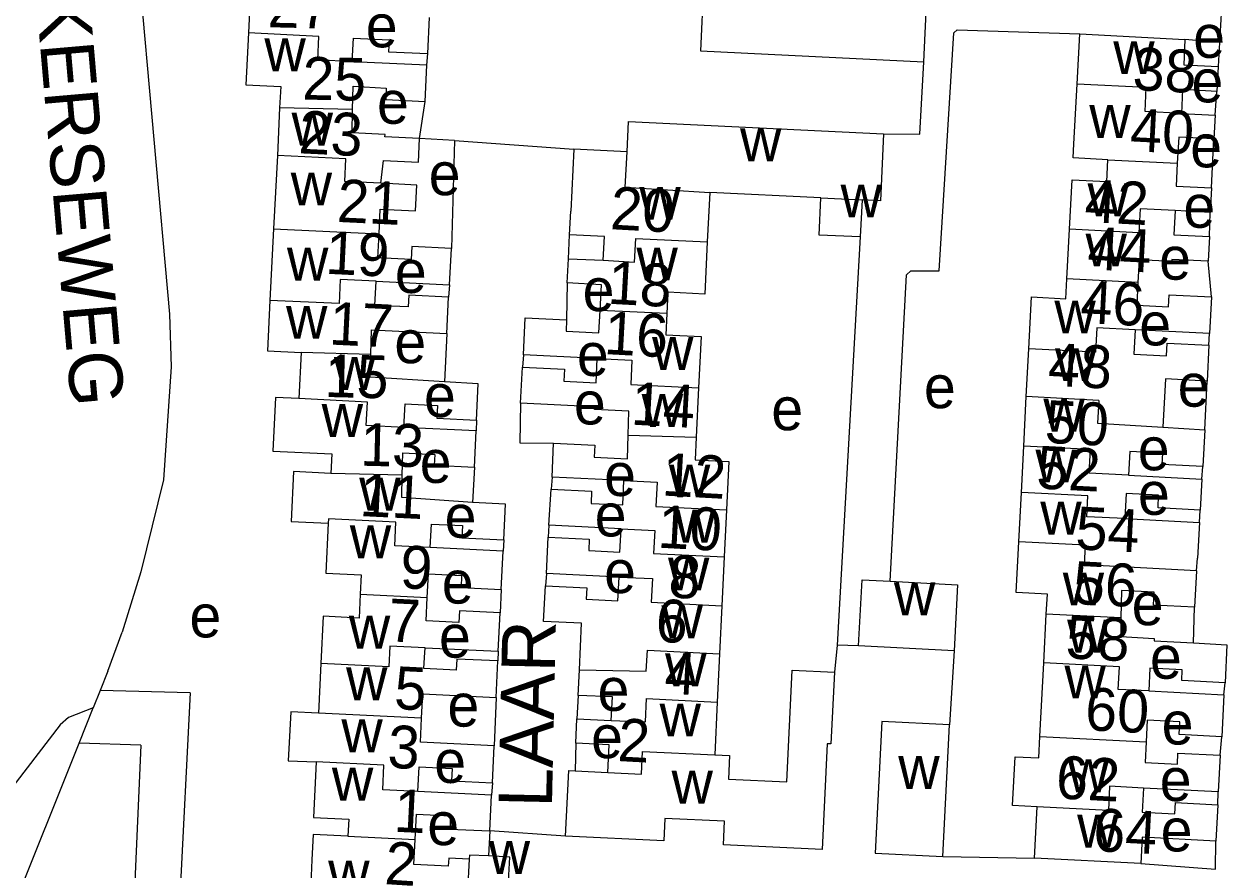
# Model space of a CAD drawing. Extents: x 163026 to 166241, y 382475 to 384501.
# Drawn here: x 164331.2 to 164443.6, y 383663 to 383742 of the extents above; entities that cross this region are included whole.
import ezdxf

# ---------------------------------------------------------------- set-up
doc = ezdxf.new("R2010")
doc.units = 0
for name, color, linetype in [('BLT_Basislijn', 7, 'Continuous'), ('BLT_Bebouwing', 7, 'Continuous'), ('BLT_Centroide', 7, 'Continuous'), ('BLT_Huisnummer', 7, 'Continuous'), ('BLT_Huisnummer_ tussenligend', 7, 'Continuous'), ('BLT_Onderverdeling_panden', 7, 'Continuous'), ('BLT_Straatnaam', 7, 'Continuous')]:
    doc.layers.add(name, color=color, linetype=linetype)

msp = doc.modelspace()

# ---------------------------------------------------------------- linework, layer by layer
at = {"layer": 'BLT_Basislijn'}
for p, q in [((164443.1, 383743.49), (164442.92, 383740.26)), ((164442.92, 383740.26), (164439.68, 383740.54)), ((164442.92, 383740.26), (164442.79, 383738)), ((164368.85, 383738.12), (164368.93, 383739.21)), ((164368.17, 383731.29), (164368.68, 383734.75)), ((164442.51, 383733.46), (164442.67, 383735.69)), ((164371.42, 383731.11), (164368.17, 383731.29)), ((164371.42, 383731.11), (164371.14, 383721.02)), ((164371.42, 383731.11), (164382.57, 383730.29)), ((164382.57, 383730.29), (164382.29, 383724.49)), ((164387.55, 383730.05), (164382.57, 383730.29)), ((164442.16, 383726.67), (164442.39, 383731.24)), ((164441.97, 383722.13), (164442.04, 383724.38)), ((164382.08, 383720.06), (164382.18, 383722.29)), ((164409.34, 383722.09), (164407.18, 383683.98)), ((164442.15, 383716.5), (164441.85, 383719.82)), ((164381.97, 383717.79), (164381.9, 383714.34)), ((164370.96, 383717.62), (164370.88, 383716.48)), ((164370.72, 383713.08), (164370.49, 383708.57)), ((164441.92, 383711.98), (164441.98, 383713.06)), ((164377.88, 383711.08), (164377.77, 383709.94)), ((164441.53, 383704.08), (164441.75, 383708.63)), ((164373.5, 383704.99), (164373.45, 383703.97)), ((164373.29, 383700.6), (164373.1, 383697.28)), ((164441.24, 383699.48), (164441.35, 383700.65)), ((164380.54, 383699.66), (164380.45, 383698.53)), ((164441.03, 383695.42), (164441.09, 383696.58)), ((164380.24, 383695.17), (164380.18, 383694.06)), ((164376.05, 383693.81), (164375.98, 383692.74)), ((164440.77, 383690.9), (164440.86, 383692.09)), ((164380.02, 383690.65), (164379.92, 383689.52)), ((164375.8, 383689.18), (164375.69, 383686.98)), ((164440.49, 383684.17), (164440.57, 383687.5)), ((164339.05, 383681.53), (164340.37, 383685.18)), ((164375.52, 383683.41), (164375.49, 383682.49)), ((164407.18, 383683.98), (164406.92, 383681.45)), ((164409.19, 383683.9), (164407.18, 383683.98)), ((164418.12, 383683.44), (164417.69, 383676.52)), ((164339.05, 383681.53), (164338.33, 383679.74)), ((164338.33, 383679.74), (164337.68, 383678.11)), ((164346.72, 383679.51), (164338.33, 383679.74)), ((164443.32, 383679.33), (164443.42, 383680.46)), ((164346.72, 383679.51), (164343.92, 383624)), ((164375.33, 383679.07), (164375.15, 383674.56)), ((164382.99, 383679.28), (164382.87, 383677.09)), ((164336.35, 383674.8), (164337.68, 383678.11)), ((164442.97, 383673.68), (164443.12, 383675.42)), ((164342.12, 383674.64), (164336.35, 383674.8)), ((164342.12, 383674.64), (164340.03, 383627.27)), ((164382.76, 383674.82), (164382.71, 383672.22)), ((164374.99, 383671.1), (164374.89, 383669.96)), ((164442.74, 383669.05), (164442.79, 383670.26)), ((164381.8, 383666.12), (164374.73, 383666.61)), ((164417.05, 383664.23), (164425.62, 383664.07))]:
    msp.add_line(p, q, dxfattribs=at)
for points in [[(164341.78, 383755.48), (164341.89, 383747.55), (164344.79, 383714.89), (164344.95, 383709.95), (164344.23, 383699.4), (164342.12, 383690.8), (164340.37, 383685.18)], [(164412.12, 383689.93), (164413.66, 383718.55), (164414.07, 383718.93), (164416.72, 383718.93), (164418.08, 383741.15), (164418.4, 383741.42), (164429.84, 383741.05)], [(164411.52, 383731.71), (164414.92, 383731.68), (164415.28, 383738.46)], [(164377.6, 383706.56), (164377.54, 383702.86), (164380.69, 383702.82)], [(164337.68, 383678.11), (164335.37, 383677.2), (164334.58, 383676.53), (164314.42, 383650.27)], [(164340.03, 383627.27), (164325.55, 383639.16), (164324.19, 383640.57), (164323.75, 383643.4), (164336.35, 383674.8)], [(164374.73, 383666.61), (164374.6, 383664.28)], [(164435.54, 383663.56), (164442.52, 383663.06), (164442.57, 383665.66)]]:
    msp.add_lwpolyline(points, dxfattribs=at)
at = {"layer": 'BLT_Bebouwing'}
for p, q in [((164352.38, 383745.55), (164352.17, 383741.15)), ((164415.28, 383738.46), (164415.58, 383744.61)), ((164368.93, 383739.21), (164369.09, 383742.59)), ((164429.6, 383736.37), (164429.84, 383741.05)), ((164429.84, 383741.05), (164439.68, 383740.54)), ((164368.68, 383734.75), (164368.85, 383738.12)), ((164442.79, 383738), (164442.67, 383735.69)), ((164355.09, 383734.15), (164354.88, 383729.71)), ((164442.51, 383733.46), (164442.39, 383731.24)), ((164387.39, 383726.75), (164387.55, 383730.05)), ((164395.28, 383726.24), (164395.05, 383721.63)), ((164405.67, 383725.74), (164395.28, 383726.24)), ((164442.16, 383726.67), (164442.04, 383724.38)), ((164409.51, 383725.55), (164409.34, 383722.09)), ((164382.18, 383722.29), (164382.29, 383724.49)), ((164428.65, 383718.17), (164428.89, 383722.82)), ((164441.97, 383722.13), (164441.85, 383719.82)), ((164370.96, 383717.62), (164371.14, 383721.02)), ((164381.97, 383717.79), (164382.08, 383720.06)), ((164382.08, 383720.06), (164385.33, 383719.91)), ((164370.72, 383713.08), (164370.88, 383716.48)), ((164442.15, 383716.5), (164441.98, 383713.06)), ((164357.09, 383711.31), (164356.88, 383706.99)), ((164424.85, 383707.18), (164425.09, 383711.65)), ((164441.92, 383711.98), (164441.75, 383708.63)), ((164377.6, 383706.56), (164377.77, 383709.94)), ((164394.24, 383708.01), (164394.02, 383703.4)), ((164424.61, 383702.56), (164424.85, 383707.18)), ((164437.6, 383704.33), (164441.53, 383704.08)), ((164373.29, 383700.6), (164373.45, 383703.97)), ((164441.53, 383704.08), (164441.35, 383700.65)), ((164380.54, 383699.66), (164380.69, 383702.82)), ((164424.39, 383698.23), (164424.61, 383702.56)), ((164441.24, 383699.48), (164441.09, 383696.58)), ((164380.24, 383695.17), (164380.45, 383698.53)), ((164424.15, 383693.63), (164424.39, 383698.23)), ((164396.85, 383696.59), (164396.63, 383692.2)), ((164441.03, 383695.42), (164440.86, 383692.09)), ((164380.02, 383690.65), (164380.18, 383694.06)), ((164375.8, 383689.18), (164375.98, 383692.74)), ((164396.63, 383692.2), (164396.41, 383687.65)), ((164440.77, 383690.9), (164440.57, 383687.5)), ((164396.41, 383687.65), (164396.2, 383683.16)), ((164375.52, 383683.41), (164375.69, 383686.98)), ((164426.49, 383682.31), (164426.72, 383686.87)), ((164396.2, 383683.16), (164395.98, 383678.65)), ((164418.12, 383683.44), (164409.19, 383683.9)), ((164358.95, 383682.24), (164358.73, 383677.62)), ((164375.33, 383679.07), (164375.49, 383682.49)), ((164382.99, 383679.28), (164383.11, 383681.65)), ((164443.32, 383679.33), (164443.12, 383675.42)), ((164382.76, 383674.82), (164382.87, 383677.09)), ((164417.05, 383664.23), (164417.69, 383676.52)), ((164374.99, 383671.1), (164375.15, 383674.56)), ((164442.97, 383673.68), (164442.79, 383670.26)), ((164382.71, 383672.22), (164385.76, 383672.07)), ((164374.73, 383666.61), (164374.89, 383669.96)), ((164425.62, 383664.07), (164425.87, 383668.88)), ((164442.74, 383669.05), (164442.57, 383665.66)), ((164435.54, 383663.56), (164425.62, 383664.07))]:
    msp.add_line(p, q, dxfattribs=at)
for points in [[(164394.7, 383745.62), (164394.41, 383739.47), (164415.28, 383738.46)], [(164352.17, 383741.15), (164351.93, 383736.3), (164355.19, 383736.14), (164355.09, 383734.15)], [(164361.87, 383738.46), (164361.98, 383740.66), (164365.32, 383740.5), (164365.26, 383739.38), (164368.93, 383739.21)], [(164439.68, 383740.54), (164439.56, 383738.17), (164442.79, 383738)], [(164368.85, 383738.12), (164361.87, 383738.46)], [(164361.91, 383733.99), (164361.96, 383736.16), (164365.06, 383736), (164365.01, 383734.93), (164368.68, 383734.75)], [(164432.48, 383729.3), (164429.24, 383729.47), (164429.31, 383730.78), (164429.6, 383736.37)], [(164442.67, 383735.69), (164439.46, 383735.86), (164439.35, 383733.62)], [(164368.17, 383731.29), (164364.93, 383731.45), (164364.94, 383731.67), (164361.86, 383731.82), (164361.91, 383733.99)], [(164439.35, 383733.62), (164442.51, 383733.46)], [(164387.55, 383730.05), (164387.68, 383732.86), (164411.52, 383731.71)], [(164364.55, 383727.1), (164364.8, 383729.22), (164368.06, 383729.06), (164368.17, 383731.29)], [(164411.52, 383731.71), (164411.22, 383725.47), (164409.51, 383725.55)], [(164442.39, 383731.24), (164439.09, 383731.41), (164438.96, 383728.97)], [(164354.88, 383729.71), (164354.53, 383722.86)], [(164428.89, 383722.82), (164429.13, 383727.44), (164432.38, 383727.27), (164432.48, 383729.3)], [(164438.96, 383728.97), (164438.85, 383726.84), (164442.16, 383726.67)], [(164364.38, 383722.38), (164364.49, 383724.7), (164367.8, 383724.54), (164367.92, 383726.94), (164364.55, 383727.1)], [(164409.34, 383722.09), (164405.5, 383722.27), (164405.67, 383725.74)], [(164438.77, 383724.55), (164438.65, 383722.3), (164441.97, 383722.13)], [(164442.04, 383724.38), (164438.77, 383724.55)], [(164354.53, 383722.86), (164354.19, 383716.17)], [(164371.14, 383721.02), (164367.43, 383721.2), (164367.37, 383719.98), (164364.27, 383720.13), (164364.38, 383722.38)], [(164385.33, 383719.91), (164385.44, 383722.13), (164382.18, 383722.29)], [(164395.05, 383721.63), (164394.82, 383716.76), (164391.37, 383716.93), (164391.28, 383714.93)], [(164441.85, 383719.82), (164438.46, 383719.99), (164438.45, 383719.79), (164435.4, 383719.95), (164435.29, 383717.83)], [(164370.88, 383716.48), (164367.15, 383716.66), (164367.1, 383715.55), (164363.99, 383715.7), (164364.1, 383717.95)], [(164364.1, 383717.95), (164370.96, 383717.62)], [(164385.03, 383715.23), (164385.15, 383717.63), (164381.97, 383717.79)], [(164425.09, 383711.65), (164425.34, 383716.49), (164428.55, 383716.32), (164428.65, 383718.17)], [(164435.29, 383717.83), (164435.18, 383715.71), (164438.15, 383715.56), (164438.21, 383716.7), (164442.15, 383716.5)], [(164354.19, 383716.17), (164353.96, 383711.46), (164357.09, 383711.31)], [(164377.88, 383711.08), (164378.04, 383714.53), (164381.9, 383714.34)], [(164381.9, 383714.34), (164381.85, 383713.3), (164384.93, 383713.15), (164385.03, 383715.23)], [(164391.28, 383714.93), (164391.18, 383712.94), (164394.48, 383712.78), (164394.24, 383708.01)], [(164363.62, 383711.11), (164363.68, 383713.43), (164370.72, 383713.08)], [(164435.02, 383713.42), (164434.91, 383711.13), (164437.94, 383710.98), (164438, 383712.18), (164441.92, 383711.98)], [(164441.98, 383713.06), (164435.02, 383713.42)], [(164370.49, 383708.57), (164363.55, 383709), (164363.62, 383711.11)], [(164384.77, 383710.75), (164377.88, 383711.08)], [(164377.77, 383709.94), (164381.7, 383709.75), (164381.64, 383708.62), (164384.66, 383708.47), (164384.77, 383710.75)], [(164441.75, 383708.63), (164437.85, 383708.83), (164437.6, 383704.33)], [(164373.5, 383704.99), (164373.64, 383708.37), (164370.49, 383708.57)], [(164356.88, 383706.99), (164354.71, 383707.09), (164354.46, 383702.08), (164359.96, 383701.82), (164359.87, 383700.01)], [(164387.66, 383703.59), (164387.73, 383705.81), (164384.5, 383705.96), (164384.51, 383706.22), (164377.6, 383706.56)], [(164366.7, 383704.3), (164366.81, 383706.49), (164369.84, 383706.35), (164369.78, 383705.18), (164373.5, 383704.99)], [(164373.45, 383703.97), (164366.7, 383704.3)], [(164380.69, 383702.82), (164384.53, 383702.63), (164384.48, 383701.52), (164387.6, 383701.37), (164387.66, 383703.59)], [(164394.02, 383703.4), (164393.92, 383701.27), (164397.07, 383701.11), (164396.85, 383696.59)], [(164441.35, 383700.65), (164437.55, 383700.85), (164437.61, 383701.89), (164434.52, 383702.05), (164434.41, 383699.84)], [(164366.55, 383699.84), (164366.6, 383701.92), (164369.58, 383701.78), (164369.53, 383700.78), (164373.29, 383700.6)], [(164359.87, 383700.01), (164356.4, 383700.18), (164356.18, 383695.53), (164359.64, 383695.36)], [(164373.1, 383697.28), (164366.5, 383697.76), (164366.55, 383699.84)], [(164434.41, 383699.84), (164441.24, 383699.48)], [(164380.45, 383698.53), (164384.24, 383698.34), (164384.19, 383697.21), (164387.15, 383697.06), (164387.26, 383699.34)], [(164387.26, 383699.34), (164380.54, 383699.66)], [(164441.09, 383696.58), (164437.16, 383696.79), (164437.22, 383697.97), (164434.19, 383698.13), (164434.07, 383695.78)], [(164376.05, 383693.81), (164376.21, 383697.12), (164373.1, 383697.28)], [(164359.64, 383695.36), (164359.42, 383690.68), (164362.7, 383690.52), (164362.61, 383688.73)], [(164434.07, 383695.78), (164441.03, 383695.42)], [(164369.17, 383693.08), (164369.27, 383695.28), (164372.18, 383695.14), (164372.12, 383694), (164376.05, 383693.81)], [(164380.18, 383694.06), (164384.02, 383693.88), (164383.97, 383692.8), (164386.89, 383692.66), (164386.99, 383694.84)], [(164386.99, 383694.84), (164380.24, 383695.17)], [(164375.98, 383692.74), (164369.17, 383693.08)], [(164426.72, 383686.87), (164426.82, 383688.74), (164423.91, 383688.89), (164424.15, 383693.63)], [(164368.88, 383688.43), (164368.99, 383690.62), (164372.09, 383690.47), (164372.04, 383689.36), (164375.8, 383689.18)], [(164379.92, 383689.52), (164383.8, 383689.33), (164383.74, 383688.26), (164386.69, 383688.11), (164386.8, 383690.33)], [(164386.8, 383690.33), (164380.02, 383690.65)], [(164409.19, 383683.9), (164409.51, 383690.07), (164412.12, 383689.93)], [(164412.12, 383689.93), (164418.44, 383689.6), (164418.12, 383683.44)], [(164362.61, 383688.73), (164362.51, 383686.49), (164359.17, 383686.66), (164358.95, 383682.24)], [(164383.11, 383681.65), (164383.3, 383686.01), (164379.76, 383686.18), (164379.92, 383689.52)], [(164440.57, 383687.5), (164436.74, 383687.7), (164436.8, 383688.91), (164433.74, 383689.07), (164433.7, 383686.51)], [(164375.69, 383686.98), (164371.9, 383687.17), (164371.85, 383686.08), (164368.77, 383686.23), (164368.88, 383688.43)], [(164433.7, 383686.51), (164433.68, 383684.76), (164436.81, 383684.6), (164436.79, 383684.37), (164440.49, 383684.17)], [(164440.49, 383684.17), (164443.6, 383684.01), (164443.42, 383680.46)], [(164368.63, 383682.81), (164368.68, 383683.73)], [(164368.68, 383683.73), (164375.52, 383683.41)], [(164375.49, 383682.49), (164371.65, 383682.67), (164371.6, 383681.64), (164368.58, 383681.78), (164368.63, 383682.81)], [(164426.13, 383675.45), (164426.49, 383682.31)], [(164443.42, 383680.46), (164439.38, 383680.67), (164439.43, 383681.65), (164436.41, 383681.81), (164436.31, 383679.7)], [(164406.92, 383681.45), (164406.59, 383674.74), (164406.26, 383674.76), (164405.78, 383664.87), (164396.55, 383665.32), (164396.66, 383667.52), (164391.09, 383667.79), (164390.98, 383665.68), (164381.8, 383666.12)], [(164395.74, 383673.73), (164397.13, 383673.67), (164397.02, 383671.46), (164402.48, 383671.19), (164402.99, 383681.64), (164406.92, 383681.45)], [(164436.31, 383679.7), (164443.32, 383679.33)], [(164368.35, 383677.15), (164368.46, 383679.41), (164375.33, 383679.07)], [(164386.08, 383676.94), (164386.19, 383679.13), (164382.99, 383679.28)], [(164395.98, 383678.65), (164395.74, 383673.73)], [(164358.73, 383677.62), (164356.15, 383677.73), (164355.9, 383673.17), (164358.51, 383673.06)], [(164375.15, 383674.56), (164368.24, 383674.9), (164368.35, 383677.15)], [(164382.87, 383677.09), (164386.08, 383676.94)], [(164417.69, 383676.52), (164411.37, 383676.85), (164410.74, 383664.55), (164417.05, 383664.23)], [(164443.12, 383675.42), (164439.13, 383675.62), (164439.19, 383676.8), (164436.15, 383676.96), (164436.05, 383674.93)], [(164425.87, 383668.88), (164423.56, 383669), (164423.8, 383673.55), (164426.03, 383673.44), (164426.13, 383675.45)], [(164385.76, 383672.07), (164385.88, 383674.67), (164382.76, 383674.82)], [(164436.05, 383674.93), (164435.95, 383673), (164438.97, 383672.84), (164439.02, 383673.88), (164442.97, 383673.68)], [(164358.51, 383673.06), (164358.25, 383667.87), (164361.55, 383667.71), (164361.47, 383666.14)], [(164368.01, 383670.3), (164368.12, 383672.6), (164371.21, 383672.45), (164371.16, 383671.28), (164374.99, 383671.1)], [(164381.8, 383666.12), (164382.1, 383672.25), (164382.71, 383672.22)], [(164435.81, 383670.62), (164435.69, 383668.36), (164438.73, 383668.2), (164438.79, 383669.26), (164442.74, 383669.05)], [(164442.79, 383670.26), (164435.81, 383670.62)], [(164374.89, 383669.96), (164368.01, 383670.3)], [(164367.76, 383665.83), (164367.87, 383668.17), (164371.05, 383668.02), (164370.99, 383666.79), (164374.73, 383666.61)], [(164361.47, 383666.14), (164358.23, 383666.29), (164358.11, 383663.91), (164357.9, 383659.43)], [(164372.81, 383663.98), (164370.89, 383664.07), (164370.85, 383663.34), (164367.64, 383663.49), (164367.76, 383665.83)], [(164442.57, 383665.66), (164435.67, 383666.02), (164435.54, 383663.56)], [(164374.6, 383664.28), (164372.83, 383664.36), (164372.81, 383663.98)], [(164376.42, 383660.8), (164376.59, 383664.18), (164374.6, 383664.28)]]:
    msp.add_lwpolyline(points, dxfattribs=at)
at = {"layer": 'BLT_Onderverdeling_panden'}
for p, q in [((164361.91, 383733.99), (164355.09, 383734.15)), ((164432.48, 383729.3), (164438.96, 383728.97)), ((164387.39, 383726.75), (164395.28, 383726.24)), ((164405.67, 383725.74), (164409.51, 383725.55)), ((164354.53, 383722.86), (164364.38, 383722.38)), ((164435.29, 383717.83), (164428.65, 383718.17)), ((164391.28, 383714.93), (164385.03, 383715.23)), ((164363.62, 383711.11), (164357.09, 383711.31)), ((164431.63, 383706.83), (164424.85, 383707.18)), ((164387.66, 383703.59), (164394.02, 383703.4)), ((164366.55, 383699.84), (164359.87, 383700.01)), ((164362.61, 383688.73), (164368.88, 383688.43)), ((164433.7, 383686.51), (164426.72, 383686.87)), ((164368.35, 383677.15), (164358.73, 383677.62)), ((164426.13, 383675.45), (164436.05, 383674.93)), ((164361.47, 383666.14), (164367.76, 383665.83))]:
    msp.add_line(p, q, dxfattribs=at)
for points in [[(164361.87, 383738.46), (164358.65, 383738.62), (164358.76, 383740.82), (164352.17, 383741.15)], [(164439.35, 383733.62), (164435.95, 383733.8), (164436.06, 383736.04), (164429.6, 383736.37)], [(164364.55, 383727.1), (164361.18, 383727.26), (164361.29, 383729.39), (164354.88, 383729.71)], [(164438.77, 383724.55), (164435.49, 383724.72), (164435.37, 383722.47), (164428.89, 383722.82)], [(164385.33, 383719.91), (164388.25, 383719.72), (164388.36, 383721.96), (164395.05, 383721.63)], [(164364.1, 383717.95), (164360.75, 383718.11), (164360.64, 383715.86), (164354.19, 383716.17)], [(164435.02, 383713.42), (164431.43, 383713.61), (164431.31, 383711.33), (164425.09, 383711.65)], [(164384.77, 383710.75), (164388, 383710.59), (164387.89, 383708.32), (164394.24, 383708.01)], [(164366.7, 383704.3), (164363.18, 383704.47), (164363.29, 383706.67), (164356.88, 383706.99)], [(164431.63, 383706.83), (164431.52, 383704.71), (164437.6, 383704.33)], [(164434.41, 383699.84), (164430.72, 383700.03), (164430.84, 383702.24), (164424.61, 383702.56)], [(164387.26, 383699.34), (164390.35, 383699.19), (164390.24, 383696.91), (164396.85, 383696.59)], [(164434.07, 383695.78), (164430.51, 383695.96), (164430.61, 383697.91), (164424.39, 383698.23)], [(164369.17, 383693.08), (164365.84, 383693.24), (164365.94, 383695.45), (164359.66, 383695.76), (164359.64, 383695.36)], [(164386.99, 383694.84), (164390.14, 383694.69), (164390.03, 383692.52), (164396.63, 383692.2)], [(164440.77, 383690.9), (164430.28, 383691.47), (164430.37, 383693.31), (164424.15, 383693.63)], [(164386.8, 383690.33), (164389.92, 383690.18), (164389.81, 383687.97), (164396.41, 383687.65)], [(164368.68, 383683.73), (164365.38, 383683.88), (164365.29, 383681.94), (164358.95, 383682.24)], [(164383.11, 383681.65), (164389.35, 383681.53), (164389.45, 383683.49), (164396.2, 383683.16)], [(164436.31, 383679.7), (164433.45, 383679.84), (164433.56, 383681.95), (164426.49, 383682.31)], [(164386.08, 383676.94), (164389.27, 383676.79), (164389.38, 383678.97), (164395.98, 383678.65)], [(164385.76, 383672.07), (164388.91, 383671.92), (164389.01, 383674.05), (164395.74, 383673.73)], [(164368.01, 383670.3), (164364.73, 383670.46), (164364.84, 383672.75), (164358.51, 383673.06)], [(164435.81, 383670.62), (164432.64, 383670.79), (164432.52, 383668.53), (164425.87, 383668.88)], [(164372.81, 383663.98), (164372.66, 383660.98)]]:
    msp.add_lwpolyline(points, dxfattribs=at)

# ---------------------------------------------------------------- texts
at = {"layer": 'BLT_Centroide'}
for s, p in [('e', (164363.14, 383739.8)), ('e', (164440.45, 383738.82)), ('w', (164353.67, 383737.56)), ('w', (164432.98, 383737.3)), ('e', (164440.29, 383734.66)), ('e', (164364.19, 383732.66)), ('w', (164356.21, 383730.62)), ('w', (164430.74, 383731.34)), ('w', (164398.11, 383729.16)), ('e', (164440.17, 383728.59)), ('e', (164369.02, 383725.99)), ('w', (164356.13, 383725.03)), ('w', (164388.7, 383723.69)), ('w', (164407.5, 383723.91)), ('w', (164430.58, 383724.03)), ('e', (164439.53, 383722.95)), ('w', (164430.39, 383719.34)), ('e', (164437.27, 383718.1)), ('w', (164355.78, 383718.01)), ('w', (164388.43, 383718.03)), ('e', (164365.86, 383716.86)), ('e', (164383.4, 383715.16)), ('w', (164355.69, 383712.58)), ('w', (164427.48, 383713.08)), ('e', (164435.41, 383711.96)), ('e', (164365.81, 383710.3)), ('e', (164382.87, 383709.11)), ('w', (164389.89, 383709.68)), ('w', (164427.54, 383708.63)), ('w', (164360.16, 383707.81)), ('e', (164415.29, 383706.1)), ('e', (164439, 383706.24)), ('e', (164368.58, 383705.27)), ('e', (164382.59, 383704.58)), ('w', (164388.92, 383704.34)), ('e', (164401.03, 383704.04)), ('w', (164426.45, 383703.92)), ('w', (164359.02, 383703.41)), ('e', (164435.27, 383700.3)), ('e', (164368.18, 383699.12)), ('w', (164425.71, 383699.16)), ('e', (164385.41, 383697.9)), ('w', (164391.46, 383697.76)), ('w', (164362.53, 383696.53)), ('e', (164435.29, 383696.14)), ('e', (164370.51, 383694)), ('e', (164384.53, 383694.12)), ('w', (164391.99, 383693.55)), ('w', (164426.16, 383694.3)), ('w', (164361.65, 383692.09)), ('e', (164385.41, 383688.83)), ('w', (164391.38, 383689.08)), ('e', (164370.24, 383687.85)), ('w', (164412.49, 383686.75)), ('w', (164428.26, 383687.68)), ('e', (164434.7, 383685.83)), ('e', (164346.67, 383684.69)), ('w', (164390.76, 383684.61)), ('w', (164361.56, 383683.64)), ('w', (164428.67, 383683.28)), ('e', (164369.98, 383682.8)), ('w', (164391.11, 383680.12)), ('e', (164436.41, 383680.83)), ('w', (164361.3, 383678.82)), ('w', (164428.42, 383678.99)), ('e', (164384.8, 383677.83)), ('e', (164370.77, 383676.36)), ('w', (164390.59, 383675.44)), ('e', (164437.5, 383674.69)), ('w', (164360.86, 383673.97)), ('e', (164384.19, 383673.41)), ('e', (164369.54, 383671.1)), ('w', (164412.89, 383670.53)), ('w', (164428.73, 383670.23)), ('w', (164359.98, 383669.44)), ('w', (164391.71, 383669.17)), ('e', (164437.32, 383669.41)), ('e', (164368.89, 383665.29)), ('w', (164429.61, 383665.05)), ('e', (164437.41, 383664.7)), ('w', (164374.62, 383662.59)), ('w', (164359.63, 383660.76))]:
    msp.add_text(s, height=4, dxfattribs=at).set_placement(p)
at = {"layer": 'BLT_Huisnummer'}
for s, rotation, p in [('38', 357.0397, (164434.73, 383735.83)), ('25', 358.6481, (164357.18, 383734.93)), ('21', 357.2306, (164360.4, 383723.5)), ('20', 356.8858, (164385.92, 383722.82)), ('42', 357.0397, (164430.24, 383723.5)), ('46', 357.0397, (164429.85, 383714.07)), ('17', 357.2035, (164359.66, 383712.05)), ('14', 356.8858, (164387.86, 383704.57)), ('50', 357.0397, (164426.52, 383702.87)), ('13', 358.6101, (164362.59, 383700.73)), ('10', 356.8858, (164390.35, 383693.08)), ('54', 357.0397, (164429.39, 383692.93)), ('9', 357.2124, (164366.29, 383689.3)), ('6', 356.8858, (164390.16, 383684.3)), ('58', 357.0397, (164428.47, 383682.75)), ('5', 357.2193, (164365.74, 383678.01)), ('2', 356.8858, (164386.61, 383673.15)), ('1', 357.22, (164365.71, 383666.55)), ('64', 357.0397, (164431.04, 383664.75)), ('2', 356.3019, (164364.83, 383661.66))]:
    msp.add_text(s, height=4, rotation=rotation, dxfattribs=at).set_placement(p)
at = {"layer": 'BLT_Huisnummer_ tussenligend'}
for s, rotation, p in [('27', 358.6481, (164353.95, 383741.68)), ('23', 357.2306, (164356.81, 383729.91)), ('40', 357.0397, (164434.48, 383730.12)), ('19', 357.2035, (164359.31, 383718.66)), ('44', 357.0397, (164430.51, 383719.07)), ('18', 356.8858, (164385.68, 383715.86)), ('16', 356.8858, (164385.34, 383711.16)), ('15', 358.6101, (164359.27, 383707.15)), ('48', 357.0397, (164426.82, 383708.21)), ('52', 357.0397, (164425.74, 383698.61)), ('12', 356.8858, (164390.75, 383697.95)), ('11', 357.2124, (164362.51, 383696.03)), ('8', 356.8858, (164391.36, 383688.43)), ('56', 357.0397, (164429.14, 383687.83)), ('7', 357.2193, (164365.17, 383684.33)), ('4', 356.8858, (164390.99, 383679.46)), ('60', 357.0397, (164430.28, 383676.04)), ('3', 357.22, (164365.12, 383672.52)), ('62', 357.0397, (164427.56, 383669.66))]:
    msp.add_text(s, height=4, rotation=rotation, dxfattribs=at).set_placement(p)
at = {"layer": 'BLT_Straatnaam'}
for s, rotation, p in [('BROEKAKKERSEWEG', 274.9501, (164329.52, 383776.79)), ('LAAR', 88.7608, (164380.53, 383668.76))]:
    msp.add_text(s, height=5, rotation=rotation, dxfattribs=at).set_placement(p)

doc.saveas('drawing.dxf')
